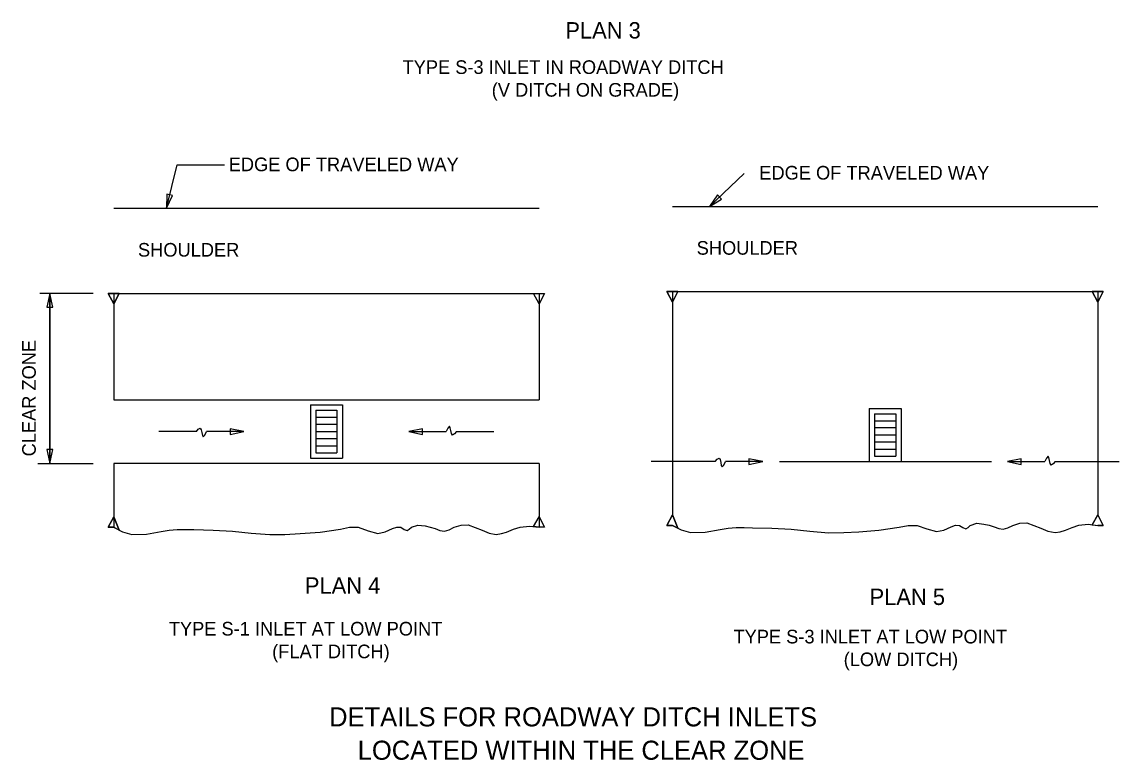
# Model space of a CAD drawing. Extents: x -437.4 to -407.9, y -458.1 to -438.
# Drawn here: x -437.18 to -425.11, y -457.54 to -449.42 of the extents above; entities that cross this region are included whole.
import ezdxf

# ---------------------------------------------------------------- set-up
doc = ezdxf.new("R2010")
doc.units = 0
doc.layers.add('Common-Notes', color=7, linetype='Continuous')
doc.layers.add('Level 4', color=7, linetype='Continuous')

msp = doc.modelspace()

# ---------------------------------------------------------------- linework, layer by layer
at = {"layer": 'Level 4'}
for p, q in [((-435.586, -451.468), (-435.468, -450.991)), ((-435.468, -450.991), (-434.947, -450.991)), ((-429.613, -451.447), (-429.231, -451.085)), ((-436.166, -451.468), (-431.487, -451.468)), ((-430.021, -451.447), (-425.342, -451.447)), ((-436.392, -452.404), (-436.979, -452.404)), ((-436.869, -454.276), (-436.869, -452.404)), ((-436.869, -452.404), (-436.869, -454.276)), ((-436.166, -452.521), (-436.228, -452.404)), ((-436.228, -452.404), (-436.166, -452.404)), ((-436.166, -452.404), (-431.487, -452.404)), ((-436.106, -452.404), (-436.166, -452.521)), ((-436.166, -452.404), (-436.166, -453.575)), ((-431.487, -452.521), (-431.549, -452.404)), ((-431.487, -452.404), (-431.426, -452.404)), ((-431.426, -452.404), (-431.487, -452.521)), ((-431.487, -452.404), (-431.487, -453.575)), ((-430.021, -452.501), (-430.081, -452.384)), ((-430.081, -452.384), (-430.021, -452.384)), ((-430.021, -452.384), (-425.342, -452.384)), ((-429.96, -452.384), (-430.021, -452.501)), ((-430.021, -452.384), (-430.021, -454.841)), ((-425.342, -452.501), (-425.402, -452.384)), ((-425.342, -452.384), (-425.281, -452.384)), ((-425.281, -452.384), (-425.342, -452.501)), ((-425.342, -452.384), (-425.342, -454.841)), ((-436.166, -453.575), (-431.487, -453.575)), ((-434.003, -453.632), (-433.651, -453.632)), ((-434.003, -453.632), (-434.003, -454.218)), ((-433.944, -453.691), (-433.71, -453.691)), ((-433.944, -453.691), (-433.944, -454.159)), ((-433.71, -453.691), (-433.71, -454.159)), ((-433.651, -453.632), (-433.651, -454.218)), ((-427.857, -453.671), (-427.857, -454.255)), ((-427.857, -453.671), (-427.506, -453.671)), ((-427.799, -453.728), (-427.565, -453.728)), ((-427.799, -453.728), (-427.799, -454.197)), ((-427.565, -453.728), (-427.565, -454.197)), ((-427.506, -453.671), (-427.506, -454.255)), ((-433.944, -453.768), (-433.71, -453.768)), ((-433.71, -453.847), (-433.944, -453.847)), ((-427.799, -453.807), (-427.565, -453.807)), ((-435.257, -453.925), (-435.67, -453.925)), ((-434.733, -453.925), (-435.145, -453.925)), ((-433.944, -453.925), (-433.71, -453.925)), ((-432.921, -453.925), (-432.509, -453.925)), ((-432.397, -453.925), (-431.985, -453.925)), ((-427.565, -453.885), (-427.799, -453.885)), ((-427.799, -453.962), (-427.565, -453.962)), ((-433.71, -454.004), (-433.944, -454.004)), ((-433.944, -454.081), (-433.71, -454.081)), ((-427.565, -454.041), (-427.799, -454.041)), ((-433.944, -454.159), (-433.71, -454.159)), ((-427.799, -454.119), (-427.565, -454.119)), ((-427.799, -454.197), (-427.565, -454.197)), ((-437.002, -454.276), (-436.392, -454.276)), ((-436.166, -454.276), (-436.166, -454.978)), ((-431.487, -454.276), (-436.166, -454.276)), ((-434.003, -454.218), (-433.651, -454.218)), ((-431.487, -454.276), (-431.487, -454.978)), ((-429.551, -454.255), (-430.255, -454.255)), ((-429.027, -454.255), (-429.438, -454.255)), ((-428.842, -454.255), (-426.51, -454.255)), ((-427.857, -454.255), (-427.506, -454.255)), ((-426.336, -454.255), (-425.924, -454.255)), ((-425.812, -454.255), (-425.108, -454.255)), ((-436.166, -454.862), (-436.228, -454.978)), ((-436.107, -455.008), (-436.166, -454.862)), ((-431.548, -454.971), (-431.487, -454.862)), ((-431.487, -454.862), (-431.426, -454.978)), ((-430.021, -454.841), (-430.081, -454.958)), ((-429.962, -454.987), (-430.021, -454.841)), ((-425.403, -454.95), (-425.342, -454.841)), ((-425.342, -454.841), (-425.281, -454.958)), ((-436.228, -454.978), (-436.166, -454.978)), ((-431.426, -454.978), (-431.487, -454.978)), ((-430.081, -454.958), (-430.02, -454.958)), ((-425.281, -454.958), (-425.342, -454.958))]:
    msp.add_line(p, q, dxfattribs=at)
for points in [[(-435.58, -451.313), (-435.586, -451.468), (-435.519, -451.328)], [(-429.524, -451.32), (-429.613, -451.447), (-429.481, -451.366)], [(-436.837, -452.556), (-436.869, -452.404), (-436.9, -452.556)], [(-436.228, -452.404), (-436.166, -452.521), (-436.106, -452.404)], [(-431.426, -452.404), (-431.487, -452.521), (-431.549, -452.404)], [(-430.081, -452.384), (-430.021, -452.501), (-429.96, -452.384)], [(-425.402, -452.384), (-425.342, -452.501), (-425.281, -452.384)], [(-434.885, -453.957), (-434.733, -453.925), (-434.885, -453.893)], [(-432.769, -453.893), (-432.921, -453.925), (-432.769, -453.957)], [(-436.9, -454.124), (-436.869, -454.276), (-436.837, -454.124)], [(-429.179, -454.287), (-429.027, -454.255), (-429.179, -454.224)], [(-426.184, -454.224), (-426.336, -454.255), (-426.184, -454.287)], [(-436.228, -454.978), (-436.166, -454.862), (-436.107, -455.008), (-436.167, -454.978)], [(-431.548, -454.971), (-431.487, -454.862), (-431.426, -454.978), (-431.487, -454.978)], [(-430.081, -454.958), (-430.021, -454.841), (-429.962, -454.987), (-430.02, -454.958)], [(-425.281, -454.958), (-425.342, -454.841), (-425.403, -454.95), (-425.342, -454.957)]]:
    msp.add_lwpolyline(points, close=True, dxfattribs=at)
for points in [[(-435.257, -453.925), (-435.236, -453.9), (-435.215, -453.887), (-435.203, -453.904), (-435.196, -453.936), (-435.19, -453.969), (-435.182, -453.984), (-435.163, -453.963), (-435.145, -453.925)], [(-432.397, -453.925), (-432.418, -453.95), (-432.439, -453.963), (-432.451, -453.946), (-432.458, -453.914), (-432.464, -453.882), (-432.472, -453.866), (-432.491, -453.887), (-432.509, -453.925)], [(-425.812, -454.255), (-425.833, -454.281), (-425.854, -454.293), (-425.867, -454.277), (-425.874, -454.244), (-425.879, -454.212), (-425.888, -454.196), (-425.907, -454.217), (-425.924, -454.255)], [(-429.551, -454.255), (-429.53, -454.23), (-429.508, -454.218), (-429.496, -454.234), (-429.489, -454.267), (-429.484, -454.299), (-429.475, -454.314), (-429.456, -454.294), (-429.438, -454.255)], [(-430.02, -454.958), (-429.924, -455.007), (-429.82, -455.036), (-429.659, -455.033), (-429.497, -455.003), (-429.409, -454.989), (-429.321, -454.982), (-429.23, -454.981), (-429.139, -454.983), (-428.926, -454.989), (-428.714, -455), (-428.509, -455.021), (-428.304, -455.038), (-428.137, -455.037), (-427.97, -455.027), (-427.749, -455.01), (-427.527, -454.977), (-427.428, -454.958), (-427.33, -454.957), (-427.222, -454.995), (-427.115, -455.024), (-427.035, -455.008), (-426.953, -454.973), (-426.907, -454.955), (-426.863, -454.957), (-426.826, -454.981), (-426.792, -454.994), (-426.769, -454.98), (-426.746, -454.957), (-426.674, -454.933), (-426.595, -454.942), (-426.538, -454.955), (-426.483, -454.973), (-426.432, -454.992), (-426.382, -455), (-426.33, -454.984), (-426.278, -454.957), (-426.201, -454.932), (-426.123, -454.93), (-425.967, -454.989), (-425.89, -455.022), (-425.812, -455.036), (-425.755, -455.028), (-425.698, -455.009), (-425.624, -454.979), (-425.55, -454.954), (-425.446, -454.945), (-425.342, -454.957)], [(-436.167, -454.978), (-436.069, -455.028), (-435.965, -455.057), (-435.805, -455.054), (-435.643, -455.024), (-435.555, -455.01), (-435.467, -455.002), (-435.376, -455.001), (-435.285, -455.004), (-435.072, -455.009), (-434.859, -455.021), (-434.655, -455.042), (-434.45, -455.058), (-434.283, -455.057), (-434.115, -455.048), (-433.894, -455.031), (-433.673, -454.998), (-433.574, -454.978), (-433.476, -454.978), (-433.367, -455.016), (-433.261, -455.045), (-433.181, -455.029), (-433.099, -454.993), (-433.053, -454.976), (-433.008, -454.978), (-432.972, -455.001), (-432.938, -455.014), (-432.915, -455), (-432.891, -454.978), (-432.819, -454.953), (-432.741, -454.963), (-432.684, -454.976), (-432.629, -454.993), (-432.578, -455.012), (-432.527, -455.021), (-432.475, -455.005), (-432.423, -454.978), (-432.346, -454.953), (-432.268, -454.951), (-432.112, -455.01), (-432.036, -455.043), (-431.958, -455.057), (-431.901, -455.048), (-431.844, -455.03), (-431.77, -454.999), (-431.695, -454.975), (-431.592, -454.965), (-431.487, -454.978)]]:
    msp.add_lwpolyline(points, dxfattribs=at)

# ---------------------------------------------------------------- texts
at = {"layer": 'Common-Notes'}
for s, height, p in [('PLAN 3', 0.18, (-431.198, -449.6)), ('PLAN 4', 0.18, (-434.063, -455.709)), ('PLAN 5', 0.18, (-427.852, -455.833)), ('DETAILS FOR ROADWAY DITCH INLETS', 0.21, (-433.797, -457.169)), ('LOCATED WITHIN THE CLEAR ZONE', 0.21, (-433.482, -457.536))]:
    msp.add_text(s, height=height, dxfattribs=at).set_placement(p)
at = {"layer": 'Level 4'}
for s, p in [('TYPE S-3 INLET IN ROADWAY DITCH', (-432.989, -449.99)), ('(V DITCH ON GRADE)', (-432.008, -450.24)), ('EDGE OF TRAVELED WAY', (-434.901, -451.06)), ('EDGE OF TRAVELED WAY', (-429.065, -451.152)), ('SHOULDER', (-435.899, -452)), ('SHOULDER', (-429.754, -451.979)), ('TYPE S-1 INLET AT LOW POINT', (-435.56, -456.169)), ('TYPE S-3 INLET AT LOW POINT', (-429.349, -456.256)), ('(FLAT DITCH)', (-434.423, -456.419)), ('(LOW DITCH)', (-428.137, -456.506))]:
    msp.add_text(s, height=0.15, dxfattribs=at).set_placement(p)
msp.add_text('CLEAR ZONE', height=0.15, rotation=90, dxfattribs=at).set_placement((-437.023, -454.198))

doc.saveas('drawing.dxf')
